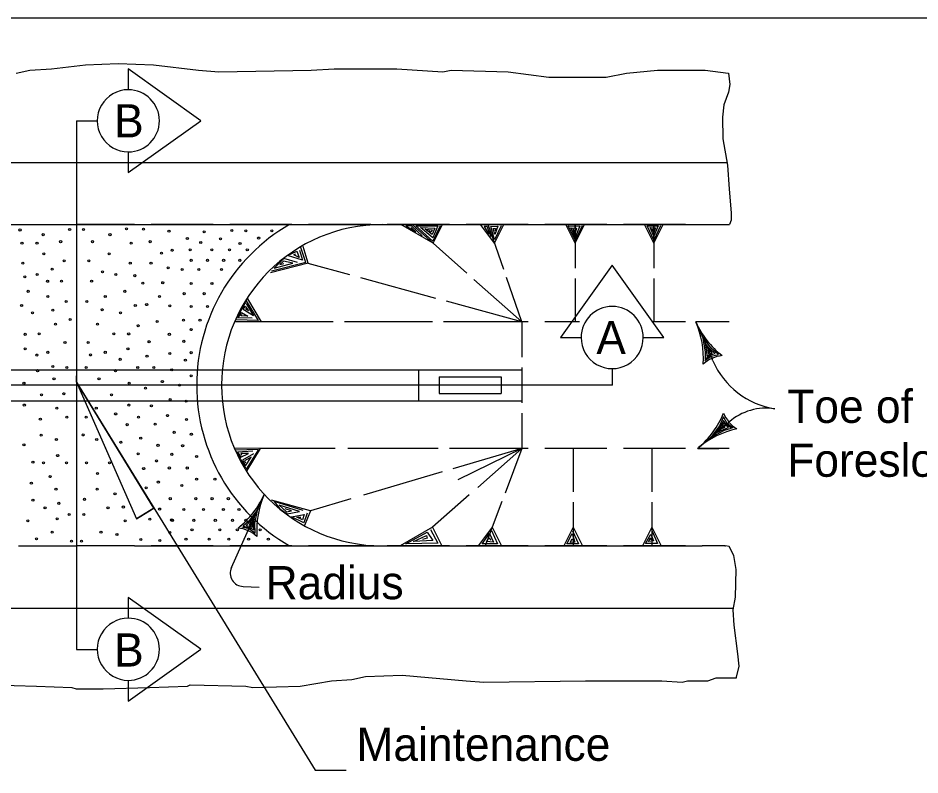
# Model space of a CAD drawing. Extents: x -772 to 772, y -957 to 657.
# Drawn here: x -404.8 to 30.5, y 292.3 to 657.5 of the extents above; entities that cross this region are included whole.
import ezdxf

# ---------------------------------------------------------------- set-up
doc = ezdxf.new("R2010")
doc.units = 0
for name, color, linetype in [('Default', 7, 'Continuous'), ('dsnCellElements', 7, 'Continuous'), ('dsnStdSection', 7, 'Continuous'), ('Level 2', 7, 'Continuous'), ('Level 3', 7, 'Continuous'), ('Level 4', 7, 'Continuous')]:
    doc.layers.add(name, color=color, linetype=linetype)

msp = doc.modelspace()

# ---------------------------------------------------------------- linework, layer by layer
at = {"layer": 'Default'}
for p, q in [((-746.08, 557.84), (-61.91, 557.84)), ((-348.58, 402.84), (-74.58, 402.84))]:
    msp.add_line(p, q, dxfattribs=at)
for radius, start, end in [(89.5, 120.0119, 180), (77.5, 90, 180), (89.5, 180, 239.9881), (77.5, 180, 270)]:
    msp.add_arc((-229.08, 480.34), radius, start, end, dxfattribs=at)
at = {"layer": 'dsnCellElements'}
msp.add_lwpolyline([(-772.5, 657.5), (-772.5, -657.5), (772.5, -657.5), (772.5, 657.5), (-772.5, 657.5)], dxfattribs=at)
at = {"layer": 'dsnStdSection'}
for points in [[(-351.58, 592.92), (-351.58, 582.92), (-316.58, 607.92), (-351.58, 632.92), (-351.58, 622.92)], [(-103.02, 503.34), (-93.02, 503.34), (-118.02, 538.34), (-143.02, 503.34), (-133.02, 503.34)], [(-351.58, 337.92), (-351.58, 327.92), (-316.58, 352.92), (-351.58, 377.92), (-351.58, 367.92)]]:
    msp.add_lwpolyline(points, dxfattribs=at)
for centre, start, end in [((-351.58, 607.92), 89.9992, 270.0008), ((-351.58, 607.92), 270.0008, 89.9992), ((-118.02, 503.34), 0.0008, 179.9992), ((-118.02, 503.34), 179.9992, 0.0008), ((-351.58, 352.92), 89.9992, 270.0008), ((-351.58, 352.92), 270.0008, 89.9992)]:
    msp.add_arc(centre, 15, start, end, dxfattribs=at)
at = {"layer": 'Level 2'}
for p, q in [((-62.09, 630.98), (-61.82, 630.9)), ((-376.58, 607.84), (-366.58, 607.84)), ((-376.58, 607.84), (-376.58, 352.84)), ((-747.03, 587.84), (-62.6, 587.84)), ((-404.58, 557.84), (-376.58, 557.84)), ((-348.58, 557.84), (-376.58, 557.84)), ((-310.58, 557.84), (-340.58, 557.84)), ((-272.58, 557.84), (-302.58, 557.84)), ((-234.58, 557.84), (-264.58, 557.84)), ((-196.58, 557.84), (-226.58, 557.84)), ((-204.4, 548.84), (-220.06, 557.84)), ((-188.17, 534.44), (-214.54, 557.84)), ((-204.52, 549.87), (-212.72, 557.28)), ((-212.72, 557.28), (-202.21, 557.18)), ((-204.4, 557.84), (-208.9, 557.84)), ((-204.4, 557.84), (-199.9, 557.84)), ((-204.4, 548.84), (-199.9, 557.84)), ((-158.58, 557.84), (-188.58, 557.84)), ((-174.75, 548.84), (-181.54, 557.84)), ((-174.75, 557.84), (-179.25, 557.84)), ((-170.36, 536.18), (-177.87, 557.84)), ((-174.75, 557.84), (-170.25, 557.84)), ((-174.75, 548.84), (-170.25, 557.84)), ((-120.58, 557.84), (-150.58, 557.84)), ((-135.93, 557.84), (-140.43, 557.84)), ((-135.93, 548.84), (-140.43, 557.84)), ((-135.93, 557.84), (-135.93, 536.84)), ((-135.93, 548.84), (-135.93, 557.84)), ((-135.93, 557.84), (-131.43, 557.84)), ((-135.93, 548.84), (-131.43, 557.84)), ((-132.52, 557.28), (-135.91, 550.3)), ((-82.58, 557.84), (-112.58, 557.84)), ((-97.93, 557.84), (-102.43, 557.84)), ((-97.93, 548.84), (-102.43, 557.84)), ((-97.93, 557.84), (-97.93, 536.84)), ((-97.93, 548.84), (-97.93, 557.84)), ((-97.93, 557.84), (-93.43, 557.84)), ((-97.93, 548.84), (-93.43, 557.84)), ((-82.58, 557.84), (-74.58, 557.84)), ((-74.58, 557.84), (-61.91, 557.84)), ((-61.91, 557.84), (-61.46, 557.86)), ((-214.8, 557.04), (-217.58, 557.18)), ((-217.58, 557.18), (-212.82, 554.31)), ((-212.82, 554.31), (-214.99, 556.38)), ((-209.75, 552.47), (-214.8, 557.04)), ((-204.66, 551.53), (-210.56, 556.48)), ((-210.56, 556.48), (-203.62, 556.15)), ((-204.99, 553.08), (-208.29, 555.63)), ((-208.29, 555.63), (-204.9, 555.25)), ((-205.32, 554.21), (-206.45, 554.83)), ((-204.9, 555.25), (-205.32, 554.21)), ((-203.62, 556.15), (-204.99, 553.08)), ((-202.21, 557.18), (-204.66, 551.53)), ((-200.98, 557.23), (-204.52, 549.87)), ((-178.42, 556.92), (-179.74, 556.88)), ((-179.74, 556.88), (-177.53, 553.2)), ((-176.39, 551.92), (-178.42, 556.92)), ((-176.58, 556.88), (-173.19, 557.02)), ((-174.79, 550.56), (-176.58, 556.88)), ((-174.6, 553.1), (-175.55, 556.03)), ((-175.55, 556.03), (-174.41, 556.03)), ((-171.68, 557.16), (-174.79, 550.56)), ((-173.19, 557.02), (-174.6, 553.1)), ((-174.41, 556.03), (-174.56, 554.85)), ((-135.91, 550.3), (-139.31, 557.23)), ((-139.31, 557.23), (-133.65, 557.09)), ((-135.87, 551.81), (-138.04, 556.33)), ((-138.04, 556.33), (-135.21, 556.14)), ((-136.62, 555.29), (-136.86, 555.72)), ((-136.01, 553.46), (-136.62, 555.29)), ((-135.21, 556.14), (-136.01, 553.46)), ((-133.65, 557.09), (-135.87, 551.81)), ((-97.9, 550.32), (-101.06, 557.16)), ((-101.06, 557.16), (-95.83, 557.16)), ((-97.86, 552.21), (-99.67, 556.4)), ((-99.67, 556.4), (-97.15, 556.28)), ((-97.95, 554.04), (-98.73, 555.74)), ((-97.15, 556.28), (-97.95, 554.04)), ((-94.67, 557.2), (-97.9, 550.32)), ((-95.83, 557.16), (-97.86, 552.21)), ((-274.82, 542.87), (-270.29, 545.04)), ((-270.29, 545.04), (-269.07, 542.02)), ((-268.97, 545.51), (-267.46, 540.7)), ((-265.92, 539.49), (-268.23, 546.79)), ((-264.79, 539.18), (-267.12, 547.23)), ((-276.52, 541.55), (-281.14, 536.74)), ((-276.61, 540.14), (-278.4, 538.63)), ((-272.18, 539.29), (-276.61, 540.14)), ((-269.91, 539.57), (-276.52, 541.55)), ((-267.46, 540.7), (-274.82, 542.87)), ((-271.71, 543.25), (-270.91, 543.77)), ((-269.07, 542.02), (-271.71, 543.25)), ((-264.79, 539.18), (-282.97, 534.5)), ((-265.92, 539.49), (-282.54, 535.42)), ((-281.14, 536.74), (-272.18, 539.29)), ((-278.4, 538.63), (-276.57, 539.05)), ((-244.65, 533.62), (-264.78, 539.14)), ((-203.11, 522.23), (-239.41, 532.19)), ((-161.58, 510.84), (-184.76, 531.42)), ((-161.58, 510.84), (-169.02, 532.31)), ((-135.93, 531.84), (-135.93, 510.84)), ((-97.93, 531.84), (-97.93, 510.84)), ((-297.13, 516.48), (-294.88, 520.38)), ((-296.1, 516.92), (-295.13, 518.42)), ((-295.13, 518.42), (-293.52, 516.29)), ((-294.71, 519.7), (-291.22, 513.87)), ((-288.67, 511.6), (-294.52, 521)), ((-287.36, 510.84), (-293.91, 522.07)), ((-161.58, 510.84), (-198.01, 520.83)), ((-297.13, 516.48), (-299.38, 512.59)), ((-298.62, 512.93), (-297.03, 515.49)), ((-297.13, 513.81), (-296.79, 514.59)), ((-293.93, 513.7), (-297.13, 513.81)), ((-297.03, 515.49), (-293.93, 513.7)), ((-291.22, 513.87), (-296.1, 516.92)), ((-293.52, 516.29), (-295.03, 517.27)), ((-287.36, 510.84), (-300.38, 510.87)), ((-288.67, 511.6), (-299.76, 511.94)), ((-291.79, 512.68), (-298.62, 512.93)), ((-252.76, 510.84), (-287.36, 510.84)), ((-204.78, 510.84), (-247.19, 510.84)), ((-161.58, 510.84), (-199.37, 510.84)), ((-158.58, 510.84), (-161.58, 510.84)), ((-161.58, 510.84), (-161.58, 493.84)), ((-133.82, 510.84), (-150.58, 510.84)), ((-82.58, 510.84), (-98.66, 510.84)), ((-74.58, 510.84), (-77.66, 510.84)), ((-77.66, 510.84), (-69.84, 493.29)), ((-61.58, 510.84), (-74.58, 510.84)), ((-69.43, 492.11), (-69.84, 493.29)), ((-161.58, 488.84), (-161.58, 471.84)), ((-117.94, 480.34), (-117.94, 488.34)), ((-376.58, 481.84), (-376.54, 484.94)), ((-117.94, 480.34), (-673.22, 480.34)), ((-376.58, 481.84), (-261.42, 294.62)), ((-376.58, 481.84), (-347.62, 415.88)), ((-161.58, 466.84), (-161.58, 449.84)), ((-76.81, 449.84), (-61.66, 462.56)), ((-287.95, 449.83), (-300.49, 449.89)), ((-288.81, 449.34), (-299.99, 449.03)), ((-291.55, 448.49), (-298.84, 448.1)), ((-288.81, 449.34), (-294.72, 439.9)), ((-287.95, 449.83), (-294.34, 439.23)), ((-251.72, 449.84), (-287.94, 449.84)), ((-202.05, 449.84), (-245.63, 449.84)), ((-161.58, 449.84), (-196.6, 449.84)), ((-161.58, 449.84), (-194.86, 440.03)), ((-161.58, 449.84), (-192.56, 434.74)), ((-161.58, 449.84), (-182.93, 431.06)), ((-161.58, 449.84), (-169.71, 428.27)), ((-158.58, 449.84), (-161.58, 449.84)), ((-120.58, 449.84), (-150.58, 449.84)), ((-136.92, 449.84), (-136.92, 428.84)), ((-82.58, 449.84), (-112.58, 449.84)), ((-98.92, 449.84), (-98.92, 428.84)), ((-61.58, 449.84), (-76.81, 449.84)), ((-76.58, 449.84), (-66.58, 449.84)), ((-297.33, 444.42), (-299.58, 448.31)), ((-298.84, 448.1), (-297.21, 445.66)), ((-297.33, 444.42), (-295.08, 440.52)), ((-293.59, 447.31), (-297.31, 447.34)), ((-297.31, 447.34), (-297.02, 446.64)), ((-297.21, 445.66), (-293.59, 447.31)), ((-291.18, 447.29), (-296.52, 444.1)), ((-296.52, 444.1), (-294.97, 441.4)), ((-292.23, 445.7), (-295.49, 443.82)), ((-294.97, 441.4), (-292.23, 445.7)), ((-295.49, 443.82), (-295.06, 442.87)), ((-200.16, 438.47), (-238.14, 427.27)), ((-301.84, 392.37), (-285.94, 427.68)), ((-285.94, 427.68), (-293.75, 410.12)), ((-187.08, 427.4), (-204.76, 411.84)), ((-263.65, 419.75), (-282.49, 424.93)), ((-267.18, 419.89), (-281.25, 424.19)), ((-281.25, 424.19), (-278.47, 420.68)), ((-269.01, 419.45), (-278.72, 422.5)), ((-278.72, 422.5), (-275.17, 419.22)), ((-244.22, 425.48), (-263.66, 419.75)), ((-171.21, 424.29), (-179.3, 402.84)), ((-136.92, 423.84), (-136.92, 402.84)), ((-98.92, 423.84), (-98.92, 402.84)), ((-339.2, 421.06), (-347.62, 415.88)), ((-278.47, 420.68), (-274.95, 418.26)), ((-272.87, 419.72), (-275.82, 420.69)), ((-275.17, 419.22), (-272.87, 419.72)), ((-274.95, 418.26), (-269.01, 419.45)), ((-272.88, 416.79), (-266.75, 417.97)), ((-266.75, 417.97), (-267.5, 415.38)), ((-265.29, 418.63), (-266.85, 413.91)), ((-263.65, 419.75), (-266.46, 412.63)), ((-266.85, 413.91), (-272.88, 416.79)), ((-270.25, 416.61), (-268.25, 416.75)), ((-267.5, 415.38), (-270.25, 416.61)), ((-204.76, 411.84), (-220.43, 402.84)), ((-217.64, 403.76), (-207.26, 409.51)), ((-207.26, 409.51), (-204.62, 405.36)), ((-205.66, 410.64), (-202.17, 404.14)), ((-204.76, 411.84), (-200.26, 402.84)), ((-175.9, 411.84), (-182.69, 402.84)), ((-176.33, 410.17), (-173.41, 403.85)), ((-175.9, 411.84), (-171.4, 402.84)), ((-136.92, 411.84), (-141.42, 402.84)), ((-137.12, 410.15), (-134.29, 403.73)), ((-136.92, 411.84), (-136.92, 402.84)), ((-136.92, 411.84), (-132.42, 402.84)), ((-136.92, 411.02), (-136.92, 402.84)), ((-98.92, 411.84), (-103.42, 402.84)), ((-98.92, 411.84), (-98.92, 402.84)), ((-98.92, 411.84), (-94.42, 402.84)), ((-98.92, 411.02), (-98.92, 402.84)), ((-98.74, 409.86), (-96.19, 403.92)), ((-213.96, 404.99), (-207.73, 407.81)), ((-204.62, 405.36), (-213.96, 404.99)), ((-207.26, 406.59), (-209.62, 405.93)), ((-207.73, 407.81), (-207.26, 406.59)), ((-180.86, 403.76), (-177.27, 408.76)), ((-178.78, 404.99), (-177.27, 406.68)), ((-175.29, 404.61), (-178.78, 404.99)), ((-177.27, 408.76), (-175.29, 404.61)), ((-177.27, 406.68), (-176.71, 405.65)), ((-139.95, 403.73), (-137.31, 408.73)), ((-138.25, 404.49), (-137.4, 406.18)), ((-137.4, 406.18), (-136.93, 405.34)), ((-137.31, 408.73), (-135.99, 404.58)), ((-101.95, 403.92), (-99.31, 408.54)), ((-100.44, 404.86), (-99.49, 406.75)), ((-98.08, 405.24), (-100.44, 404.86)), ((-99.49, 406.75), (-99.31, 405.71)), ((-99.31, 408.54), (-98.08, 405.24)), ((-404.58, 402.84), (-376.58, 402.84)), ((-348.58, 402.84), (-376.58, 402.84)), ((-310.58, 402.84), (-340.58, 402.84)), ((-272.58, 402.84), (-302.58, 402.84)), ((-234.58, 402.84), (-264.58, 402.84)), ((-196.58, 402.84), (-226.58, 402.84)), ((-202.17, 404.14), (-217.64, 403.76)), ((-204.76, 402.84), (-209.26, 402.84)), ((-204.76, 402.84), (-200.26, 402.84)), ((-158.58, 402.84), (-188.58, 402.84)), ((-173.41, 403.85), (-180.86, 403.76)), ((-175.9, 402.84), (-180.4, 402.84)), ((-175.9, 402.84), (-171.4, 402.84)), ((-120.58, 402.84), (-150.58, 402.84)), ((-131.27, 402.84), (-142.96, 402.84)), ((-136.92, 402.84), (-141.42, 402.84)), ((-134.29, 403.73), (-139.95, 403.73)), ((-135.99, 404.58), (-138.25, 404.49)), ((-136.92, 402.84), (-132.42, 402.84)), ((-82.58, 402.84), (-112.58, 402.84)), ((-98.92, 402.84), (-103.42, 402.84)), ((-96.19, 403.92), (-101.95, 403.92)), ((-98.92, 402.84), (-94.42, 402.84)), ((-63.61, 402.84), (-74.58, 402.84)), ((-63.61, 402.84), (-63.35, 402.78)), ((-296.1, 383.27), (-288.47, 382.88)), ((-746.69, 372.84), (-59.41, 372.84)), ((-376.58, 352.84), (-366.58, 352.84)), ((-58.03, 339.07), (-57.94, 339.48)), ((-261.42, 294.62), (-246.42, 294.62))]:
    msp.add_line(p, q, dxfattribs=at)
for points in [[(-405.68, 630.96), (-399.12, 632.27), (-388.62, 632.93), (-372.22, 634.9), (-356.48, 635.55), (-339.43, 634.9), (-317.78, 632.27), (-307.94, 631.62), (-263.34, 632.27), (-252.19, 632.93), (-222.01, 632.93), (-199.71, 631.62), (-195.78, 632.27), (-168.23, 631.62), (-148.55, 628.99), (-121, 628.99), (-111.16, 630.96), (-96.07, 632.27), (-73.11, 632.27), (-62.09, 630.98)], [(-61.82, 630.9), (-61.22, 625.47), (-61.88, 621.7), (-64.17, 615.63), (-64.83, 609.73), (-64.66, 599.23), (-62.37, 586.44), (-61.55, 574.96), (-60.56, 563.48), (-60.56, 560.04), (-61.46, 557.86)], [(-73.26, 492.2), (-70.28, 494.31), (-66.68, 495.09), (-70.32, 498.18), (-74.5, 503.78), (-73.08, 496.39), (-73.08, 492.94), (-70.55, 494.92), (-68.31, 495.59), (-70.7, 497.62), (-73.12, 500.69), (-72.55, 496.53), (-72.35, 494.31), (-69.72, 495.92), (-71.92, 497.99), (-71.66, 495.71), (-70.68, 496.11), (-71.4, 496.91)], [(-59.67, 459.58), (-62.53, 461.85), (-64.26, 465.1), (-66.22, 460.75), (-70.46, 455.19), (-63.75, 458.59), (-60.42, 459.54), (-63.03, 461.43), (-64.29, 463.39), (-65.58, 460.54), (-67.86, 457.37), (-64.03, 459.06), (-61.95, 459.86), (-64.22, 461.96), (-65.61, 459.26), (-63.48, 460.14), (-64.14, 460.97), (-64.71, 460.06)], [(-296.85, 411.93), (-293.28, 411.13), (-290.3, 408.98), (-290.44, 413.75), (-289.07, 420.6), (-293.62, 414.6), (-296.19, 412.29), (-293.02, 411.73), (-291.03, 410.52), (-291.11, 413.65), (-290.45, 417.5), (-293.16, 414.3), (-294.67, 412.67), (-291.71, 411.78), (-291.65, 414.81), (-293.17, 413.09), (-292.22, 412.63), (-292.11, 413.7)], [(-57.94, 339.48), (-56.8, 344.73), (-57.45, 350.79), (-59.09, 364.57), (-59.58, 371.95), (-58.44, 378.01), (-58.11, 391.46), (-59.26, 398.18), (-61.55, 402.45), (-63.35, 402.78)], [(-341.39, 334.48), (-323.03, 335.13), (-321.72, 335.79), (-294.82, 335.13), (-291.54, 334.48), (-268.59, 335.13), (-253.5, 337.76), (-243.66, 338.41), (-237.1, 339.72), (-219.39, 340.38), (-188.56, 337.76), (-180.03, 337.1), (-130.84, 337.76), (-94.1, 337.76), (-84.27, 337.1), (-81.64, 337.76), (-71.8, 337.76), (-67.87, 339.07), (-58.03, 339.07)], [(-744.8, 334.48), (-726.43, 333.16), (-717.91, 333.16), (-707.41, 334.48), (-657.56, 336.44), (-633.95, 338.41), (-616.89, 337.76), (-605.09, 336.44), (-584.75, 334.48), (-549.33, 335.79), (-538.83, 337.1), (-502.76, 337.1), (-494.89, 335.79), (-473.24, 337.1), (-469.3, 336.44), (-466.02, 337.1), (-441.75, 337.1), (-439.13, 336.44), (-395.84, 335.13), (-378.78, 334.48), (-376.82, 333.82), (-363.7, 333.82), (-341.39, 334.48)]]:
    msp.add_lwpolyline(points, dxfattribs=at)
for centre in [(-403.85, 555.24), (-392.72, 552.99), (-379.9, 555.44), (-373.26, 555.44), (-360.44, 552.99), (-352.44, 555.79), (-344.24, 555.62), (-331.96, 554.69), (-314.99, 554.31), (-301.6, 555.01), (-294.85, 554.87), (-282.35, 554.87), (-402.91, 548.84), (-395.65, 548.89), (-384.24, 549.6), (-368.92, 549.6), (-350.25, 548.84), (-341.01, 549.6), (-323.09, 551.1), (-316.63, 549.24), (-307.08, 550.93), (-297.66, 548.68), (-288.67, 551.35), (-392.35, 543.75), (-360.81, 543.75), (-335.57, 544.03), (-330.45, 545.45), (-321.77, 545.63), (-311.29, 545.63), (-302.72, 545.63), (-294.15, 545.63), (-382.54, 540.35), (-370.62, 540.35), (-321.23, 540.59), (-313.4, 540.59), (-305.57, 540.59), (-297.74, 540.59), (-402.53, 539.22), (-388.38, 536.38), (-364.05, 535.06), (-350.63, 539.22), (-340.63, 539.22), (-332.36, 536.95), (-325.55, 536.21), (-317.54, 536.21), (-306.57, 536.21), (-401.58, 532.61), (-395.55, 533.75), (-357.61, 533.75), (-348.39, 533.18), (-390.54, 530.48), (-383.86, 530.55), (-369.3, 530.55), (-344.59, 529.6), (-334.98, 529.79), (-321.23, 529.45), (-311.21, 529.45), (-399.89, 525.64), (-390.46, 523.19), (-362.7, 523.19), (-353.27, 525.64), (-336.51, 523.18), (-324.6, 524.51), (-315.01, 524.51), (-403.09, 518.84), (-381.6, 520.74), (-371.56, 520.74), (-348.2, 518.84), (-342.71, 519.23), (-331.58, 518.67), (-321.23, 518.31), (-313.4, 518.31), (-397.81, 515.27), (-388, 516.58), (-364.24, 516.77), (-355.34, 515.27), (-386.69, 509.8), (-379.7, 512.05), (-366.47, 509.8), (-346.86, 509.05), (-337.62, 511.12), (-324.98, 511.69), (-316.98, 511.69), (-401.39, 504.88), (-394.61, 505.09), (-358.55, 505.09), (-351.41, 505.07), (-331.77, 504.9), (-321.23, 507.17), (-382.16, 500.94), (-371, 500.94), (-341.58, 501.32), (-324.79, 501.5), (-401.4, 497.92), (-390.46, 496.22), (-362.7, 496.22), (-351.76, 497.92), (-321.23, 496.03), (-395.74, 494.89), (-369.83, 494.94), (-355.56, 492.81), (-342.55, 494.32), (-331.58, 495.66), (-324.04, 492.45), (-395.36, 487.36), (-387.98, 489.32), (-381.22, 488.87), (-371.94, 488.87), (-357.8, 487.36), (-347.05, 488.87), (-339.31, 488.87), (-330.64, 487.74), (-387.44, 483.4), (-365.72, 483.4), (-321.23, 484.89), (-401.96, 481.32), (-351.2, 481.32), (-343.27, 478.87), (-335.16, 482.08), (-326.87, 480.38), (-393.48, 475.67), (-382.73, 476.23), (-359.68, 475.67), (-401.78, 470.76), (-351.38, 470.76), (-340.45, 470.39), (-331.39, 473.4), (-323.66, 472.65), (-386.12, 469.25), (-367.04, 469.25), (-357.69, 466.48), (-332.71, 465.67), (-394.04, 463.97), (-381.22, 464.92), (-371.94, 464.92), (-352.17, 461.31), (-346.67, 464.92), (-338.59, 461.5), (-323.47, 463.78), (-329.43, 457.61), (-321.15, 456.66), (-393.66, 456.22), (-386.31, 454.17), (-373.41, 456.34), (-366.85, 454.17), (-355.19, 452.8), (-345.59, 454.78), (-401.96, 451.53), (-337.24, 451.34), (-325.36, 451.15), (-385.68, 446.37), (-346.87, 447.24), (-337.97, 443.79), (-330.6, 447), (-318.62, 445.96), (-397.62, 443.21), (-392.53, 442.85), (-381.41, 442.85), (-371.75, 442.85), (-360.62, 442.85), (-344.16, 440.09), (-331.77, 440.4), (-323.12, 440.38), (-389.32, 436.23), (-366.5, 437.74), (-318.62, 434.97), (-309.77, 434.97), (-398.38, 433.04), (-342.96, 430.82), (-337.09, 433.62), (-325.73, 431.91), (-386.5, 430.22), (-366.66, 430.22), (-358.01, 427.93), (-397.62, 424.91), (-385.17, 423.36), (-372.72, 425.29), (-331.32, 425.6), (-319.04, 425.6), (-311.17, 425.6), (-303.3, 425.6), (-391.78, 421.16), (-380.09, 417.96), (-373.07, 417.96), (-361.38, 421.16), (-353.98, 421.57), (-336.48, 420.59), (-324.79, 420.41), (-324.79, 420.41), (-315.25, 420.41), (-305.7, 420.41), (-298.17, 420.41), (-400.08, 414.94), (-385.93, 415.86), (-353.08, 414.94), (-341.2, 415.69), (-330.66, 415.29), (-330.31, 415.15), (-319.95, 415.15), (-309.59, 415.15), (-301.26, 415.15), (-294.8, 415.15), (-388.38, 409.47), (-364.77, 409.47), (-331.58, 409.28), (-320.83, 410.6), (-307.38, 410.6), (-298.95, 410.6), (-287.98, 410.6), (-395.92, 406.24), (-378.96, 405.13), (-374.2, 405.13), (-357.07, 408.31), (-345.54, 405.89), (-336.34, 405.46), (-323.75, 406.03), (-312.53, 406.08), (-303.02, 406.08), (-293.51, 406.08), (-283.99, 406.08)]:
    msp.add_circle(centre, 0.5, dxfattribs=at)
for centre, radius, start, end in [((-38.83, 528.13), 42.5, 204, 232.0725), ((-116.49, 493.56), 42.5, 355.9275, 24), ((-63.17, 478.29), 16.42, 96.2666, 131.7334), ((-33.27, 507.98), 39.49, 203.7012, 260.984), ((-103.7, 482.76), 42.5, 310, 338.0725), ((-49.08, 473.11), 16.42, 202.2666, 237.7334), ((-43.64, 441.98), 27.32, 81.2035, 131.2113), ((-49.06, 417.65), 42.5, 101.9275, 130), ((-324.76, 444.96), 42.5, 307.9275, 336), ((-247.11, 410.39), 42.5, 156, 184.0725), ((-300.43, 395.12), 16.42, 48.2666, 83.7334), ((-295.96, 389.72), 6.46, 155.7432, 268.7616)]:
    msp.add_arc(centre, radius, start, end, dxfattribs=at)
at = {"layer": 'Level 4'}
for p, q in [((-591.58, 487.84), (-161.58, 487.84)), ((-211.58, 487.84), (-211.58, 472.84)), ((-201.58, 484.34), (-171.58, 484.34)), ((-201.58, 484.34), (-201.58, 476.34)), ((-171.58, 484.34), (-171.58, 476.34)), ((-201.58, 476.34), (-171.58, 476.34)), ((-591.58, 472.84), (-161.58, 472.84))]:
    msp.add_line(p, q, dxfattribs=at)
msp.add_lwpolyline([(-375.92, 480.34), (-347.62, 415.88), (-339.2, 421.06), (-375.66, 480.34)], close=True, dxfattribs=at)

# ---------------------------------------------------------------- texts
at = {"layer": 'Level 3'}
for s, p in [('B', (-358.44, 599.92)), ('A', (-125.68, 495.34)), ('Toe of', (-33.52, 462.16)), ('Foreslope', (-33.52, 436.16)), ('Radius', (-285.31, 377.08)), ('B', (-358.44, 344.58)), ('Maintenance', (-241.43, 299.1))]:
    msp.add_text(s, height=16, dxfattribs=at).set_placement(p)

doc.saveas('drawing.dxf')
